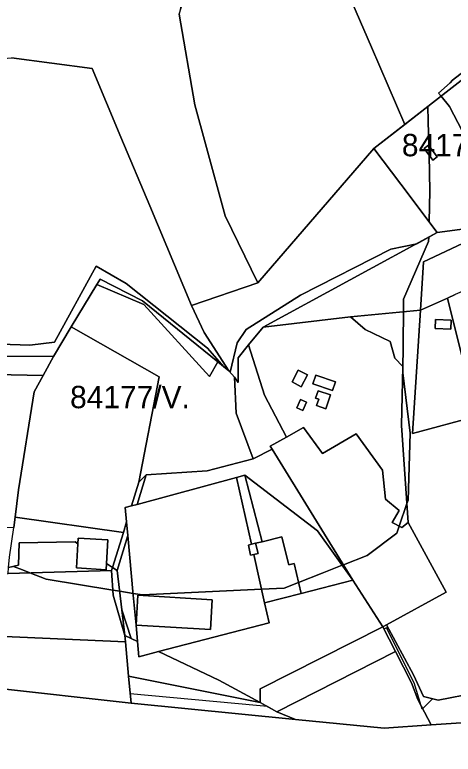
# Model space of a CAD drawing. Extents: x -477304 to -465429, y -1159113 to -1149210.
# Drawn here: x -475284.1 to -474990.2, y -1155587.8 to -1155091.9 of the extents above; entities that cross this region are included whole.
import ezdxf

# ---------------------------------------------------------------- set-up
doc = ezdxf.new("R2010")
doc.units = 0
for name, color, linetype in [('BPEJ_s', 7, 'Continuous'), ('ostatni_s', 7, 'Continuous'), ('PUPFL_s', 7, 'Continuous'), ('trav_porost_s', 7, 'Continuous')]:
    doc.layers.add(name, color=color, linetype=linetype)

msp = doc.modelspace()

# ---------------------------------------------------------------- linework, layer by layer
at = {"layer": 'BPEJ_s'}
for points in [[(-474924.57, -1155325.94), (-474927.55, -1155314.88), (-474931.16, -1155305.52), (-474935.63, -1155288.51), (-474938.6, -1155282.56), (-474944.77, -1155260.45), (-474946.68, -1155257.04), (-474954.34, -1155235.78), (-474956.68, -1155231.53), (-474959.05, -1155225.21), (-474960.39, -1155221.64), (-474970.11, -1155196.79), (-474992.61, -1155153.28), (-474998.27, -1155146.43), (-475000, -1155144.34), (-474992.19, -1155137.54), (-474990.7, -1155135.63), (-474977.09, -1155125.21), (-474965.18, -1155117.34), (-474955.4, -1155109.47), (-474942.64, -1155100.97), (-474935.78, -1155095.57), (-474930.74, -1155091.61)], [(-474977.09, -1155125.21), (-474990.7, -1155135.63), (-474992.19, -1155137.54), (-475000, -1155144.34), (-474998.27, -1155146.43), (-475000, -1155147.77), (-475004, -1155150.89), (-475007.15, -1155153.34), (-475043.44, -1155181.62), (-475025.38, -1155205.56), (-475006.39, -1155230.71), (-475000.92, -1155237.98), (-475006.67, -1155241.1), (-475014.71, -1155245.46), (-475032, -1155249), (-475092.5, -1155280), (-475129, -1155303), (-475135, -1155312), (-475139.8, -1155331.66), (-475140.62, -1155330.7), (-475144.03, -1155327.93), (-475155, -1155315.5), (-475209.5, -1155272), (-475229.5, -1155260.5), (-475257.5, -1155311.5), (-475274, -1155313.5), (-475320, -1155312)], [(-475006.92, -1155163.28), (-475007.15, -1155153.34), (-475004, -1155150.89), (-475000, -1155147.77), (-474998.27, -1155146.43), (-474992.61, -1155153.28), (-474970.11, -1155196.79)], [(-475285.04, -1155461.82), (-475279.05, -1155464.18), (-475274.14, -1155466.12), (-475263, -1155470.5), (-475218.37, -1155477.76), (-475213.79, -1155478.51), (-475204.79, -1155479.98), (-475198.5, -1155481), (-475118.67, -1155477.22), (-475103.5, -1155476.5), (-475093.85, -1155472.68), (-475078.02, -1155466.4), (-475064.66, -1155461.1), (-475063.88, -1155460.79), (-475048, -1155454.5), (-475028, -1155439.5), (-475026.43, -1155434.9), (-475021.24, -1155419.68), (-475020.5, -1155417.5), (-475019, -1155372.5), (-475024, -1155332), (-475023.59, -1155291.12), (-475023.5, -1155282.5), (-475006.75, -1155243.82), (-475006.67, -1155241.1), (-475000.92, -1155237.98), (-475006.39, -1155230.71), (-475005.83, -1155210.02), (-475006.39, -1155186.04), (-475006.45, -1155183.16), (-475006.53, -1155179.67), (-475006.92, -1155163.28)], [(-475320, -1155312), (-475274, -1155313.5), (-475257.5, -1155311.5), (-475229.5, -1155260.5), (-475209.5, -1155272), (-475155, -1155315.5), (-475144.03, -1155327.93), (-475140.62, -1155330.7), (-475139.8, -1155331.66), (-475135, -1155312), (-475129, -1155303), (-475092.5, -1155280), (-475032, -1155249), (-475014.71, -1155245.46), (-475006.67, -1155241.1), (-475006.75, -1155243.82), (-475023.5, -1155282.5), (-475023.59, -1155291.12), (-475024, -1155332), (-475019, -1155372.5), (-475020.5, -1155417.5), (-475021.24, -1155419.68), (-475026.43, -1155434.9), (-475028, -1155439.5), (-475048, -1155454.5), (-475063.88, -1155460.79), (-475064.66, -1155461.1), (-475078.02, -1155466.4), (-475093.85, -1155472.68), (-475103.5, -1155476.5), (-475118.67, -1155477.22), (-475198.5, -1155481), (-475204.79, -1155479.98), (-475213.79, -1155478.51), (-475218.37, -1155477.76), (-475263, -1155470.5), (-475274.14, -1155466.12), (-475279.05, -1155464.18), (-475285.04, -1155461.82)], [(-474975.02, -1155546.76), (-475000, -1155551.56), (-475000.41, -1155551.64), (-475004.12, -1155550.67), (-475010.7, -1155557.2), (-475011, -1155557.5), (-475011.7, -1155555.28), (-475016.5, -1155540), (-475035, -1155503), (-475036.68, -1155503.96), (-475029.02, -1155518.82), (-475108.53, -1155559.41), (-475114.82, -1155555.83), (-475122.04, -1155555.16), (-475206.72, -1155547.26), (-475206.15, -1155553.48), (-475298.74, -1155543.35)], [(-474975.02, -1155546.76), (-475000, -1155551.56), (-475000.41, -1155551.64), (-475004.12, -1155550.67), (-475010.7, -1155557.2), (-475011, -1155557.5), (-475011.7, -1155555.28), (-475016.5, -1155540), (-475035, -1155503), (-475036.68, -1155503.96), (-475029.02, -1155518.82), (-475108.53, -1155559.41), (-475114.82, -1155555.83), (-475122.04, -1155555.16), (-475206.72, -1155547.26), (-475206.15, -1155553.48), (-475298.74, -1155543.35)]]:
    msp.add_lwpolyline(points, dxfattribs=at)
msp.add_lwpolyline([(-475006.39, -1155230.71), (-475025.38, -1155205.56), (-475043.44, -1155181.62), (-475007.15, -1155153.34), (-475006.92, -1155163.28), (-475006.53, -1155179.67), (-475006.45, -1155183.16), (-475006.39, -1155186.04), (-475005.83, -1155210.02)], close=True, dxfattribs=at)
at = {"layer": 'ostatni_s'}
for points in [[(-475006.8, -1155179.32), (-475000.92, -1155187.03), (-475003.9, -1155189.3), (-475009.78, -1155181.59)], [(-474991.89, -1155302.71), (-475002.31, -1155302.29), (-475002.07, -1155296.25), (-474991.65, -1155296.67)], [(-475124.33, -1155389.7), (-475135.84, -1155359.1), (-475136.89, -1155335.03), (-475134.42, -1155338.53), (-475134.35, -1155321.88), (-475127.4, -1155313.27), (-475116.73, -1155346.94), (-475101.96, -1155375.06), (-475112.87, -1155381.16), (-475111.66, -1155383.17)], [(-475258.3, -1155321.13), (-475265.12, -1155333.72), (-475393.84, -1155331.14), (-475391.77, -1155320.42), (-475308.3, -1155320.87)], [(-475094.06, -1155330.13), (-475087.84, -1155333.45), (-475092.14, -1155341.4), (-475098.28, -1155338.1)], [(-475082.23, -1155333.55), (-475069.05, -1155338.07), (-475071.05, -1155343.91), (-475084.23, -1155339.39)], [(-475082.53, -1155348.94), (-475080.83, -1155343.99), (-475072.49, -1155346.86), (-475075.69, -1155356.15), (-475081.89, -1155354.01), (-475080.4, -1155349.67)], [(-475125.47, -1155447), (-475135.54, -1155402.22), (-475129.97, -1155400.71), (-475118.3, -1155445.29), (-475122.71, -1155446.34)], [(-475243.74, -1155445.45), (-475241.9, -1155446.72), (-475242.88, -1155462.85), (-475222.92, -1155464.06), (-475222.67, -1155459.93), (-475218.65, -1155462.69), (-475219.24, -1155464.59), (-475288.6, -1155466.52), (-475288.29, -1155462.55), (-475281.71, -1155461.08), (-475281.19, -1155446.12)], [(-475241.9, -1155446.72), (-475241.67, -1155442.89), (-475221.71, -1155444.1), (-475222.67, -1155459.93), (-475222.92, -1155464.06), (-475242.88, -1155462.85)], [(-475100.53, -1155460.88), (-475096.88, -1155460.01), (-475092.1, -1155480.03), (-475116.63, -1155486.31), (-475123.92, -1155453.87), (-475121.08, -1155453.18), (-475122.71, -1155446.34), (-475118.3, -1155445.29), (-475105.02, -1155442.11), (-475103.72, -1155447.54)], [(-475121.08, -1155453.18), (-475123.92, -1155453.87), (-475126.03, -1155454.38), (-475127.57, -1155447.5), (-475125.47, -1155447), (-475122.71, -1155446.34)], [(-475219.24, -1155464.59), (-475218.65, -1155462.69), (-475215.43, -1155464.49), (-475212.33, -1155490.97), (-475210.31, -1155508.29), (-475218.15, -1155481.12)]]:
    msp.add_lwpolyline(points, close=True, dxfattribs=at)
at = {"layer": 'PUPFL_s'}
for points in [[(-475320.81, -1154943.71), (-475284.03, -1154949.65), (-475266.98, -1154952), (-475225.73, -1154957.69), (-475219.8, -1154958.51), (-475213.59, -1154965.78), (-475198.63, -1155014.78), (-475179.88, -1155030.21), (-475177.48, -1155046.96), (-475164.66, -1155057.04), (-475169.53, -1155069.99), (-475173.99, -1155091.51), (-475163.39, -1155152.27), (-475156.26, -1155178.53), (-475143.15, -1155226.78), (-475121.3, -1155271.61), (-475165.59, -1155286.93), (-475193.64, -1155220.04), (-475212.97, -1155173.93), (-475232.3, -1155127.82), (-475286.37, -1155120.79)], [(-475298.74, -1155543.35), (-475206.15, -1155553.48), (-475095.91, -1155564.5), (-475036.44, -1155570.45), (-475005.07, -1155568.1), (-474954.64, -1155564.84), (-474904.52, -1155563.01), (-474723.24, -1155550.86), (-474692.67, -1155587.82)]]:
    msp.add_lwpolyline(points, dxfattribs=at)
for points in [[(-475111.55, -1154970.59), (-475106.78, -1154970.86), (-475091, -1155007.32), (-475065.58, -1155066.06), (-475045.05, -1155113.5), (-475022.6, -1155165.38), (-475043.44, -1155181.62), (-475121.3, -1155271.61), (-475143.15, -1155226.78), (-475156.26, -1155178.53), (-475163.39, -1155152.27), (-475173.99, -1155091.51), (-475149.73, -1155014.88), (-475134.64, -1154967.21)], [(-475056.48, -1154976.62), (-475004.27, -1154983.33), (-474958.58, -1154990.8), (-474917.07, -1154995.67), (-474874.84, -1154998.42), (-474861.16, -1155000.01), (-474853.82, -1155010.8), (-474860.92, -1155010.33), (-474867, -1155025.93), (-474861.04, -1155036.64), (-474872.83, -1155047.28), (-474880.31, -1155070.09), (-474884.82, -1155064.31), (-474910.23, -1155077.84), (-474964.56, -1155120.16), (-475004, -1155150.89), (-475022.6, -1155165.38), (-475045.05, -1155113.5), (-475065.58, -1155066.06), (-475091, -1155007.32), (-475106.78, -1154970.86), (-475089.93, -1154971.82), (-475079.65, -1154973.48), (-475059.45, -1154975.85)], [(-475165.59, -1155286.93), (-475157.25, -1155305.04), (-475140.62, -1155330.7), (-475148, -1155324.71), (-475198.47, -1155283.71), (-475226.82, -1155269.18), (-475229.05, -1155272.86), (-475246.26, -1155301.25), (-475258.3, -1155321.13), (-475308.3, -1155320.87), (-475391.77, -1155320.42), (-475387.55, -1155296.23), (-475391.09, -1155230.71), (-475373.8, -1155138.84), (-475369.33, -1155127.33), (-475319.49, -1155123.4), (-475286.37, -1155120.79), (-475232.3, -1155127.82), (-475212.97, -1155173.93), (-475193.64, -1155220.04)], [(-475121.3, -1155271.61), (-475043.44, -1155181.62), (-475025.38, -1155205.56), (-475000.92, -1155237.98), (-475117.74, -1155301.3), (-475127.4, -1155313.27), (-475134.35, -1155321.88), (-475134.42, -1155338.53), (-475136.89, -1155335.03), (-475140.62, -1155330.7), (-475157.25, -1155305.04), (-475165.59, -1155286.93)], [(-475153.69, -1155334.37), (-475197.63, -1155286.1), (-475229.05, -1155272.86), (-475226.82, -1155269.18), (-475198.47, -1155283.71), (-475148, -1155324.71)], [(-475308.58, -1155467.07), (-475288.6, -1155466.52), (-475219.24, -1155464.59), (-475218.15, -1155481.12), (-475210.31, -1155508.29), (-475209.93, -1155512.39), (-475296.18, -1155508.68), (-475298.74, -1155543.35), (-475386.25, -1155533.78), (-475381.73, -1155522.23), (-475331.64, -1155496.15), (-475364.86, -1155479.09), (-475341.61, -1155469.39)], [(-475013.9, -1155551.02), (-475018.15, -1155539.88), (-475029.02, -1155518.82), (-475037.45, -1155502.47), (-475034.92, -1155501.09), (-475016.82, -1155534.52), (-475010.17, -1155549.1), (-475000.41, -1155551.64), (-474975.02, -1155546.76), (-474963.38, -1155541.34), (-474959.09, -1155545.37), (-474938.83, -1155538.2), (-474929.69, -1155533.11), (-474927.22, -1155531.9), (-474910.07, -1155531.71), (-474888.95, -1155525.15), (-474886.64, -1155524.35), (-474888.25, -1155531.29), (-474889.07, -1155534.01), (-474904.52, -1155563.01), (-474954.64, -1155564.84), (-475005.07, -1155568.1)], [(-475029.02, -1155518.82), (-475018.15, -1155539.88), (-475013.9, -1155551.02), (-475005.07, -1155568.1), (-475036.44, -1155570.45), (-475095.91, -1155564.5), (-475108.53, -1155559.41)], [(-475119.56, -1155553.13), (-475108.53, -1155559.41), (-475095.91, -1155564.5), (-475206.15, -1155553.48), (-475207.81, -1155535.48)]]:
    msp.add_lwpolyline(points, close=True, dxfattribs=at)
at = {"layer": 'trav_porost_s'}
for points in [[(-474731.95, -1155075.85), (-474757.5, -1155109.37), (-474770.29, -1155132.53), (-474776.21, -1155115.75), (-474819.14, -1155151.33), (-474898.03, -1155195.17), (-474959.75, -1155225.56), (-474979.04, -1155235.06), (-475000.92, -1155237.98), (-475025.38, -1155205.56), (-475043.44, -1155181.62), (-475022.6, -1155165.38), (-475004, -1155150.89), (-474964.56, -1155120.16), (-474910.23, -1155077.84)], [(-474974.37, -1155361.05), (-474994.03, -1155281.83), (-474988.81, -1155279.47)], [(-474975.02, -1155546.76), (-475000.41, -1155551.64), (-475010.17, -1155549.1), (-475016.82, -1155534.52), (-475034.92, -1155501.09), (-474994.94, -1155479.23), (-475020.33, -1155432.51), (-475024.96, -1155367.38), (-475024.03, -1155327.86), (-475029.33, -1155322.14), (-475032.46, -1155311), (-475049.22, -1155303), (-475059.1, -1155294.4), (-475012.25, -1155290.07), (-475017.47, -1155372.65), (-474974.37, -1155361.05)]]:
    msp.add_lwpolyline(points, dxfattribs=at)
for points in [[(-475003.9, -1155189.3), (-475000.92, -1155187.03), (-475006.8, -1155179.32), (-475009.78, -1155181.59)], [(-475010.21, -1155257.62), (-475012.25, -1155290.07), (-475059.1, -1155294.4), (-475117.74, -1155301.3), (-475000.92, -1155237.98), (-474979.04, -1155235.06), (-474959.75, -1155225.56), (-474957.45, -1155232.67)], [(-474985.72, -1155278.07), (-474988.81, -1155279.47), (-474994.03, -1155281.83), (-475012.25, -1155290.07), (-475010.21, -1155257.62), (-474957.45, -1155232.67), (-474948.25, -1155261.11)], [(-475229.05, -1155272.86), (-475197.63, -1155286.1), (-475153.69, -1155334.37), (-475148, -1155324.71), (-475140.62, -1155330.7), (-475136.89, -1155335.03), (-475135.84, -1155359.1), (-475124.33, -1155389.7), (-475155.22, -1155397.65), (-475196.09, -1155400.47), (-475200.88, -1155405.27), (-475187.46, -1155334.66), (-475246.26, -1155301.25)], [(-475017.47, -1155372.65), (-475012.25, -1155290.07), (-474994.03, -1155281.83), (-474974.37, -1155361.05)], [(-475049.22, -1155303), (-475032.46, -1155311), (-475029.33, -1155322.14), (-475024.03, -1155327.86), (-475024.96, -1155367.38), (-475020.33, -1155432.51), (-475024.73, -1155435.85), (-475031.1, -1155432.31), (-475026.54, -1155424.31), (-475035.6, -1155416.86), (-475037.72, -1155397.34), (-475055.31, -1155373.03), (-475077.78, -1155386.06), (-475090.56, -1155368.69), (-475101.96, -1155375.06), (-475116.73, -1155346.94), (-475127.4, -1155313.27), (-475117.74, -1155301.3), (-475059.1, -1155294.4)], [(-475002.07, -1155296.25), (-475002.31, -1155302.29), (-474991.89, -1155302.71), (-474991.65, -1155296.67)], [(-475211.35, -1155439.1), (-475283.93, -1155428.83), (-475281.66, -1155410.51), (-475271.08, -1155344.74), (-475265.12, -1155333.72), (-475258.3, -1155321.13), (-475246.26, -1155301.25), (-475187.46, -1155334.66), (-475200.88, -1155405.27), (-475205.83, -1155421.27), (-475210.05, -1155422.41), (-475209.17, -1155432.05)], [(-475373.51, -1155414.97), (-475376.62, -1155385.99), (-475395.11, -1155337.73), (-475393.84, -1155331.14), (-475265.12, -1155333.72), (-475271.08, -1155344.74), (-475281.66, -1155410.51), (-475283.93, -1155428.83), (-475284.78, -1155435.65), (-475374.68, -1155438.5)], [(-475094.06, -1155330.13), (-475098.28, -1155338.1), (-475092.14, -1155341.4), (-475087.84, -1155333.45)], [(-475071.05, -1155343.91), (-475069.05, -1155338.07), (-475082.23, -1155333.55), (-475084.23, -1155339.39)], [(-475072.49, -1155346.86), (-475080.83, -1155343.99), (-475082.53, -1155348.94), (-475080.4, -1155349.67), (-475081.89, -1155354.01), (-475075.69, -1155356.15)], [(-475095.09, -1155355.43), (-475091.15, -1155357.18), (-475088.69, -1155351.66), (-475092.63, -1155349.9)], [(-475091.15, -1155357.18), (-475095.09, -1155355.43), (-475092.63, -1155349.9), (-475088.69, -1155351.66)], [(-475055.31, -1155373.03), (-475037.72, -1155397.34), (-475035.6, -1155416.86), (-475026.54, -1155424.31), (-475031.1, -1155432.31), (-475024.73, -1155435.85), (-475020.33, -1155432.51), (-474994.94, -1155479.23), (-475034.92, -1155501.09), (-475037.45, -1155502.47), (-475057.51, -1155471.15), (-475111.66, -1155383.17), (-475112.87, -1155381.16), (-475101.96, -1155375.06), (-475090.56, -1155368.69), (-475077.78, -1155386.06)], [(-475111.66, -1155383.17), (-475057.51, -1155471.15), (-475081.14, -1155437.97), (-475129.97, -1155400.71), (-475135.54, -1155402.22), (-475202.07, -1155420.25), (-475196.09, -1155400.47), (-475155.22, -1155397.65), (-475124.33, -1155389.7)], [(-475202.07, -1155420.25), (-475205.83, -1155421.27), (-475200.88, -1155405.27), (-475196.09, -1155400.47)], [(-475100.53, -1155460.88), (-475103.72, -1155447.54), (-475105.02, -1155442.11), (-475118.3, -1155445.29), (-475129.97, -1155400.71), (-475081.14, -1155437.97), (-475057.51, -1155471.15), (-475092.1, -1155480.03), (-475096.88, -1155460.01)], [(-475202.85, -1155501.19), (-475204.69, -1155481.04), (-475208.35, -1155441.04), (-475209.17, -1155432.05), (-475210.05, -1155422.41), (-475205.83, -1155421.27), (-475202.07, -1155420.25), (-475135.54, -1155402.22), (-475125.47, -1155447), (-475127.57, -1155447.5), (-475126.03, -1155454.38), (-475123.92, -1155453.87), (-475116.63, -1155486.31), (-475113.63, -1155499.66), (-475187.75, -1155518.99), (-475200.9, -1155522.42), (-475201.83, -1155512.31), (-475202.85, -1155501.19), (-475152.94, -1155504.17), (-475151.74, -1155484.2), (-475201.65, -1155481.22)], [(-475283.93, -1155428.83), (-475211.35, -1155439.1), (-475218.65, -1155462.69), (-475222.67, -1155459.93), (-475221.71, -1155444.1), (-475241.67, -1155442.89), (-475241.9, -1155446.72), (-475243.74, -1155445.45), (-475281.19, -1155446.12), (-475281.71, -1155461.08), (-475288.29, -1155462.55), (-475287.76, -1155455.69), (-475284.78, -1155435.65)], [(-475211.35, -1155439.1), (-475209.17, -1155432.05), (-475208.35, -1155441.04), (-475215.43, -1155464.49), (-475218.65, -1155462.69)], [(-475204.69, -1155481.04), (-475202.85, -1155501.19), (-475201.83, -1155512.31), (-475206.07, -1155510.3), (-475212.33, -1155490.97), (-475215.43, -1155464.49), (-475208.35, -1155441.04)], [(-475187.75, -1155518.99), (-475113.63, -1155499.66), (-475116.63, -1155486.31), (-475092.1, -1155480.03), (-475057.51, -1155471.15), (-475037.45, -1155502.47), (-475119.67, -1155544.08), (-475119.56, -1155553.13), (-475147.28, -1155538.18)], [(-475152.94, -1155504.17), (-475202.85, -1155501.19), (-475201.65, -1155481.22), (-475151.74, -1155484.2)], [(-475210.31, -1155508.29), (-475212.33, -1155490.97), (-475206.07, -1155510.3)], [(-475037.45, -1155502.47), (-475029.02, -1155518.82), (-475108.53, -1155559.41), (-475119.56, -1155553.13), (-475119.67, -1155544.08)], [(-475209.93, -1155512.39), (-475207.81, -1155535.48), (-475206.15, -1155553.48), (-475298.74, -1155543.35), (-475296.18, -1155508.68)], [(-475147.28, -1155538.18), (-475119.56, -1155553.13), (-475207.81, -1155535.48), (-475209.93, -1155512.39), (-475210.31, -1155508.29), (-475206.07, -1155510.3), (-475201.83, -1155512.31), (-475200.9, -1155522.42), (-475187.75, -1155518.99)]]:
    msp.add_lwpolyline(points, close=True, dxfattribs=at)

# ---------------------------------------------------------------- texts
at = {"layer": 'BPEJ_s'}
for p in [(-475024.64, -1155186.76), (-475247.07, -1155355.75)]:
    msp.add_text('84177/V.', height=15, dxfattribs=at).set_placement(p)

doc.saveas('drawing.dxf')
